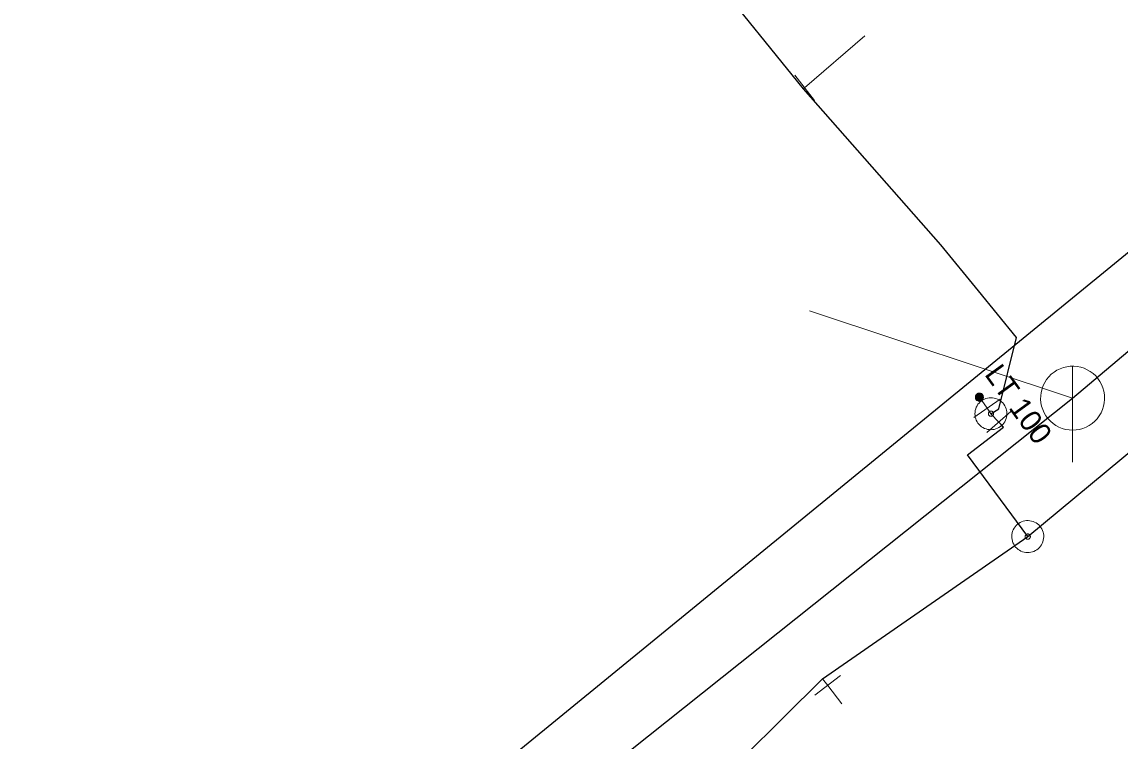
# Model space of a CAD drawing. Extents: x -688296 to -687852, y -973332 to -972816.
# Drawn here: x -688174.53 to -688140.22, y -973095.48 to -973073.01 of the extents above; entities that cross this region are included whole.
import ezdxf
from ezdxf.enums import TextEntityAlignment as Align

# ---------------------------------------------------------------- set-up
doc = ezdxf.new("R2010")
doc.units = 0
doc.header["$LTSCALE"] = 0.27
for name, color, linetype, lineweight in [('1', 7, 'Continuous', 25), ('11', 7, 'Continuous', 13), ('13', 7, 'Continuous', 13), ('14', 7, 'Continuous', 13), ('17', 7, 'Continuous', 25), ('22', 7, 'Continuous', 13), ('34', 7, 'Continuous', 13), ('47', 7, 'Continuous', 13), ('9', 7, 'Continuous', 13)]:
    doc.layers.add(name, color=color, linetype=linetype, lineweight=lineweight)

msp = doc.modelspace()

# ---------------------------------------------------------------- linework, layer by layer
at = {"layer": '11'}
msp.add_line((-688149.932, -973082.04), (-688141.706, -973084.763), dxfattribs=at)
at = {"layer": '13'}
for p, q in [((-688150.079, -973075.067), (-688148.199, -973073.44)), ((-688149.359, -973093.739), (-688148.92, -973094.32))]:
    msp.add_line(p, q, dxfattribs=at)
at = {"layer": '14', "lineweight": 25}
for p, q in [((-688141.707, -973084.764), (-688118.48, -973065.11)), ((-688173.864, -973110.353), (-688141.707, -973084.764))]:
    msp.add_line(p, q, dxfattribs=at)
at = {"layer": '14'}
for p, q in [((-688150.12, -973075.1), (-688150.079, -973075.067)), ((-688149.52, -973093.53), (-688149.359, -973093.739))]:
    msp.add_line(p, q, dxfattribs=at)
msp.add_lwpolyline([(-688144.01, -973085.51), (-688144.259, -973085.25), (-688144.379, -973085.079), (-688144.62, -973084.73)], dxfattribs=at)
at = {"layer": '17'}
for points in [[(-688123.609, -972815.609), (-688135.91, -972839.761), (-688146.524, -972867.704), (-688149.164, -972878.87), (-688150.368, -972974.473), (-688134.778, -973051.136), (-688125.903, -973068.701), (-688203.651, -973132.27), (-688148.612, -973199.748), (-688078.631, -973291.807), (-688049.631, -973331.642)], [(-688144.259, -973085.25), (-688144.01, -973085.1), (-688143.456, -973082.873), (-688144.649, -973081.41), (-688145.82, -973079.969), (-688150.12, -973075.1), (-688167.42, -973053.719)], [(-688143.109, -973089.09), (-688129.52, -973077.82), (-688116.32, -973067.34), (-688115.17, -973065.85)], [(-688143.109, -973089.09), (-688144.989, -973086.539), (-688143.87, -973085.67), (-688143.94, -973085.59), (-688144.01, -973085.51)], [(-688204.44, -973139.53), (-688204.19, -973139.309), (-688203.89, -973139.05), (-688177.64, -973116.5), (-688162.42, -973104.039), (-688153.219, -973097.199), (-688149.52, -973093.53), (-688143.109, -973089.09)]]:
    msp.add_lwpolyline(points, dxfattribs=at)
at = {"layer": '22'}
msp.add_line((-688141.707, -973086.764), (-688141.706, -973083.764), dxfattribs=at)
msp.add_lwpolyline([(-688140.707, -973084.764), (-688140.712, -973084.655), (-688140.73, -973084.547), (-688140.76, -973084.441), (-688140.8, -973084.34), (-688140.852, -973084.243), (-688140.914, -973084.153), (-688140.986, -973084.07), (-688141.066, -973083.996), (-688141.154, -973083.93), (-688141.248, -973083.875), (-688141.348, -973083.83), (-688141.453, -973083.797), (-688141.56, -973083.775), (-688141.669, -973083.765), (-688141.779, -973083.767), (-688141.887, -973083.781), (-688141.994, -973083.806), (-688142.097, -973083.843), (-688142.195, -973083.892), (-688142.287, -973083.95), (-688142.373, -973084.019), (-688142.45, -973084.096), (-688142.519, -973084.182), (-688142.578, -973084.274), (-688142.626, -973084.372), (-688142.663, -973084.475), (-688142.689, -973084.582), (-688142.703, -973084.69), (-688142.706, -973084.8), (-688142.696, -973084.909), (-688142.675, -973085.016), (-688142.641, -973085.12), (-688142.597, -973085.22), (-688142.542, -973085.315), (-688142.476, -973085.403), (-688142.402, -973085.483), (-688142.319, -973085.555), (-688142.229, -973085.617), (-688142.133, -973085.669), (-688142.031, -973085.71), (-688141.926, -973085.74), (-688141.818, -973085.758), (-688141.708, -973085.764), (-688141.599, -973085.758), (-688141.491, -973085.74), (-688141.386, -973085.711), (-688141.284, -973085.67), (-688141.187, -973085.618), (-688141.097, -973085.556), (-688141.014, -973085.485), (-688140.939, -973085.405), (-688140.874, -973085.317), (-688140.818, -973085.223), (-688140.774, -973085.123), (-688140.74, -973085.019), (-688140.718, -973084.911), (-688140.708, -973084.802)], close=True, dxfattribs=at)
at = {"layer": '34'}
for p, q in [((-688150.39, -973074.676), (-688149.767, -973075.458)), ((-688144.788, -973085.365), (-688143.968, -973084.793)), ((-688143.637, -973085.176), (-688144.383, -973085.842)), ((-688148.961, -973093.435), (-688149.757, -973094.041))]:
    msp.add_line(p, q, dxfattribs=at)
at = {"layer": '47'}
for points in [[(-688144.553, -973084.845), (-688144.593, -973084.879), (-688144.631, -973084.916), (-688144.663, -973084.956), (-688144.692, -973085), (-688144.716, -973085.047), (-688144.734, -973085.096), (-688144.747, -973085.146), (-688144.755, -973085.198), (-688144.758, -973085.25), (-688144.756, -973085.303), (-688144.747, -973085.355), (-688144.733, -973085.405), (-688144.715, -973085.454), (-688144.691, -973085.5), (-688144.663, -973085.544), (-688144.629, -973085.584), (-688144.592, -973085.622), (-688144.551, -973085.655), (-688144.508, -973085.683), (-688144.461, -973085.707), (-688144.412, -973085.725), (-688144.361, -973085.739), (-688144.309, -973085.747), (-688144.257, -973085.75), (-688144.205, -973085.747), (-688144.153, -973085.738), (-688144.103, -973085.725), (-688144.054, -973085.706), (-688144.008, -973085.682), (-688143.964, -973085.654), (-688143.924, -973085.62), (-688143.886, -973085.583), (-688143.853, -973085.543), (-688143.825, -973085.499), (-688143.801, -973085.452), (-688143.782, -973085.404), (-688143.769, -973085.353), (-688143.761, -973085.301), (-688143.758, -973085.248), (-688143.761, -973085.196), (-688143.77, -973085.144), (-688143.783, -973085.094), (-688143.802, -973085.045), (-688143.826, -973084.999), (-688143.854, -973084.955), (-688143.888, -973084.915), (-688143.925, -973084.877), (-688143.965, -973084.845), (-688144.009, -973084.816), (-688144.056, -973084.792), (-688144.104, -973084.773), (-688144.155, -973084.76), (-688144.206, -973084.752), (-688144.259, -973084.75), (-688144.312, -973084.752), (-688144.364, -973084.761), (-688144.413, -973084.774), (-688144.463, -973084.793), (-688144.509, -973084.817)], [(-688144.307, -973085.183), (-688144.314, -973085.189), (-688144.319, -973085.195), (-688144.325, -973085.201), (-688144.329, -973085.208), (-688144.333, -973085.216), (-688144.336, -973085.224), (-688144.339, -973085.233), (-688144.34, -973085.241), (-688144.34, -973085.25), (-688144.34, -973085.258), (-688144.339, -973085.267), (-688144.336, -973085.275), (-688144.333, -973085.283), (-688144.33, -973085.291), (-688144.325, -973085.298), (-688144.319, -973085.305), (-688144.313, -973085.31), (-688144.307, -973085.316), (-688144.3, -973085.32), (-688144.292, -973085.324), (-688144.284, -973085.327), (-688144.275, -973085.33), (-688144.267, -973085.331), (-688144.258, -973085.332), (-688144.25, -973085.331), (-688144.241, -973085.33), (-688144.233, -973085.327), (-688144.225, -973085.324), (-688144.217, -973085.321), (-688144.21, -973085.316), (-688144.203, -973085.31), (-688144.198, -973085.304), (-688144.192, -973085.298), (-688144.188, -973085.291), (-688144.184, -973085.283), (-688144.18, -973085.275), (-688144.178, -973085.266), (-688144.177, -973085.258), (-688144.176, -973085.249), (-688144.177, -973085.241), (-688144.178, -973085.232), (-688144.181, -973085.224), (-688144.184, -973085.216), (-688144.187, -973085.208), (-688144.192, -973085.201), (-688144.198, -973085.194), (-688144.204, -973085.189), (-688144.21, -973085.183), (-688144.217, -973085.179), (-688144.225, -973085.175), (-688144.233, -973085.171), (-688144.242, -973085.169), (-688144.25, -973085.168), (-688144.259, -973085.168), (-688144.267, -973085.168), (-688144.276, -973085.169), (-688144.284, -973085.172), (-688144.292, -973085.175), (-688144.3, -973085.178)], [(-688142.697, -973088.805), (-688142.73, -973088.764), (-688142.766, -973088.726), (-688142.806, -973088.692), (-688142.848, -973088.662), (-688142.895, -973088.637), (-688142.944, -973088.618), (-688142.994, -973088.604), (-688143.045, -973088.594), (-688143.097, -973088.59), (-688143.15, -973088.591), (-688143.202, -973088.598), (-688143.252, -973088.611), (-688143.301, -973088.628), (-688143.349, -973088.651), (-688143.393, -973088.678), (-688143.434, -973088.711), (-688143.472, -973088.747), (-688143.506, -973088.787), (-688143.536, -973088.829), (-688143.561, -973088.876), (-688143.58, -973088.925), (-688143.595, -973088.975), (-688143.604, -973089.027), (-688143.609, -973089.078), (-688143.607, -973089.131), (-688143.6, -973089.183), (-688143.587, -973089.234), (-688143.57, -973089.282), (-688143.547, -973089.33), (-688143.52, -973089.374), (-688143.487, -973089.415), (-688143.451, -973089.453), (-688143.412, -973089.488), (-688143.369, -973089.517), (-688143.322, -973089.542), (-688143.274, -973089.562), (-688143.224, -973089.577), (-688143.172, -973089.586), (-688143.12, -973089.59), (-688143.067, -973089.588), (-688143.015, -973089.581), (-688142.965, -973089.569), (-688142.916, -973089.551), (-688142.868, -973089.528), (-688142.824, -973089.501), (-688142.783, -973089.468), (-688142.745, -973089.432), (-688142.711, -973089.393), (-688142.681, -973089.35), (-688142.656, -973089.303), (-688142.636, -973089.255), (-688142.622, -973089.205), (-688142.613, -973089.154), (-688142.609, -973089.101), (-688142.61, -973089.048), (-688142.617, -973088.996), (-688142.63, -973088.946), (-688142.647, -973088.897), (-688142.67, -973088.849)], [(-688143.041, -973089.043), (-688143.046, -973089.035), (-688143.052, -973089.03), (-688143.059, -973089.025), (-688143.066, -973089.02), (-688143.073, -973089.015), (-688143.082, -973089.012), (-688143.09, -973089.01), (-688143.098, -973089.008), (-688143.107, -973089.008), (-688143.115, -973089.008), (-688143.124, -973089.009), (-688143.132, -973089.011), (-688143.14, -973089.014), (-688143.148, -973089.017), (-688143.155, -973089.022), (-688143.163, -973089.027), (-688143.168, -973089.033), (-688143.173, -973089.04), (-688143.178, -973089.047), (-688143.183, -973089.054), (-688143.186, -973089.063), (-688143.188, -973089.071), (-688143.19, -973089.079), (-688143.191, -973089.088), (-688143.19, -973089.096), (-688143.189, -973089.105), (-688143.187, -973089.113), (-688143.184, -973089.121), (-688143.181, -973089.129), (-688143.176, -973089.136), (-688143.171, -973089.144), (-688143.165, -973089.149), (-688143.158, -973089.154), (-688143.151, -973089.159), (-688143.144, -973089.164), (-688143.136, -973089.167), (-688143.127, -973089.169), (-688143.119, -973089.171), (-688143.11, -973089.172), (-688143.102, -973089.171), (-688143.093, -973089.17), (-688143.085, -973089.168), (-688143.077, -973089.165), (-688143.069, -973089.162), (-688143.062, -973089.157), (-688143.054, -973089.152), (-688143.049, -973089.146), (-688143.044, -973089.139), (-688143.039, -973089.132), (-688143.034, -973089.125), (-688143.031, -973089.117), (-688143.029, -973089.108), (-688143.027, -973089.1), (-688143.027, -973089.091), (-688143.027, -973089.083), (-688143.028, -973089.074), (-688143.03, -973089.066), (-688143.033, -973089.058), (-688143.036, -973089.05)]]:
    msp.add_lwpolyline(points, close=True, dxfattribs=at)
at = {"layer": '9'}
for points in [[(-688144.746, -973084.73), (-688144.746, -973084.743), (-688144.744, -973084.756), (-688144.741, -973084.769), (-688144.736, -973084.781), (-688144.73, -973084.793), (-688144.723, -973084.804), (-688144.715, -973084.814), (-688144.705, -973084.824), (-688144.695, -973084.832), (-688144.684, -973084.839), (-688144.672, -973084.845), (-688144.66, -973084.85), (-688144.647, -973084.853), (-688144.634, -973084.855), (-688144.621, -973084.857), (-688144.608, -973084.856), (-688144.595, -973084.854), (-688144.582, -973084.851), (-688144.57, -973084.846), (-688144.558, -973084.84), (-688144.547, -973084.833), (-688144.537, -973084.825), (-688144.527, -973084.815), (-688144.519, -973084.805), (-688144.512, -973084.794), (-688144.506, -973084.782), (-688144.501, -973084.77), (-688144.498, -973084.757), (-688144.496, -973084.744), (-688144.494, -973084.731), (-688144.495, -973084.718), (-688144.497, -973084.705), (-688144.5, -973084.692), (-688144.505, -973084.68), (-688144.511, -973084.668), (-688144.518, -973084.657), (-688144.526, -973084.647), (-688144.536, -973084.637), (-688144.546, -973084.629), (-688144.557, -973084.622), (-688144.569, -973084.616), (-688144.581, -973084.611), (-688144.594, -973084.608), (-688144.607, -973084.606), (-688144.62, -973084.605), (-688144.633, -973084.605), (-688144.646, -973084.607), (-688144.659, -973084.61), (-688144.671, -973084.615), (-688144.683, -973084.621), (-688144.694, -973084.628), (-688144.704, -973084.636), (-688144.714, -973084.646), (-688144.722, -973084.656), (-688144.729, -973084.667), (-688144.735, -973084.679), (-688144.74, -973084.691), (-688144.743, -973084.704), (-688144.745, -973084.717)], [(-688144.726, -973084.73), (-688144.727, -973084.741), (-688144.725, -973084.752), (-688144.722, -973084.763), (-688144.718, -973084.773), (-688144.713, -973084.783), (-688144.707, -973084.792), (-688144.7, -973084.801), (-688144.692, -973084.809), (-688144.683, -973084.816), (-688144.674, -973084.822), (-688144.664, -973084.827), (-688144.654, -973084.831), (-688144.643, -973084.834), (-688144.632, -973084.837), (-688144.621, -973084.837), (-688144.61, -973084.837), (-688144.599, -973084.835), (-688144.588, -973084.832), (-688144.578, -973084.828), (-688144.568, -973084.823), (-688144.559, -973084.817), (-688144.55, -973084.81), (-688144.542, -973084.802), (-688144.535, -973084.793), (-688144.529, -973084.784), (-688144.524, -973084.774), (-688144.52, -973084.764), (-688144.517, -973084.753), (-688144.515, -973084.742), (-688144.514, -973084.731), (-688144.514, -973084.72), (-688144.516, -973084.709), (-688144.519, -973084.698), (-688144.523, -973084.688), (-688144.528, -973084.678), (-688144.534, -973084.669), (-688144.541, -973084.66), (-688144.549, -973084.652), (-688144.558, -973084.645), (-688144.567, -973084.639), (-688144.577, -973084.634), (-688144.587, -973084.63), (-688144.598, -973084.627), (-688144.608, -973084.625), (-688144.62, -973084.625), (-688144.631, -973084.624), (-688144.642, -973084.626), (-688144.653, -973084.629), (-688144.663, -973084.633), (-688144.673, -973084.638), (-688144.682, -973084.644), (-688144.691, -973084.651), (-688144.699, -973084.659), (-688144.706, -973084.668), (-688144.712, -973084.677), (-688144.717, -973084.687), (-688144.721, -973084.697), (-688144.724, -973084.708), (-688144.726, -973084.719)], [(-688144.707, -973084.73), (-688144.707, -973084.739), (-688144.706, -973084.748), (-688144.703, -973084.757), (-688144.7, -973084.765), (-688144.696, -973084.773), (-688144.691, -973084.781), (-688144.684, -973084.788), (-688144.679, -973084.794), (-688144.672, -973084.8), (-688144.664, -973084.805), (-688144.656, -973084.809), (-688144.648, -973084.812), (-688144.639, -973084.815), (-688144.63, -973084.816), (-688144.621, -973084.818), (-688144.612, -973084.817), (-688144.603, -973084.816), (-688144.594, -973084.813), (-688144.586, -973084.81), (-688144.578, -973084.806), (-688144.57, -973084.801), (-688144.563, -973084.795), (-688144.557, -973084.789), (-688144.551, -973084.782), (-688144.546, -973084.774), (-688144.542, -973084.766), (-688144.539, -973084.758), (-688144.536, -973084.749), (-688144.535, -973084.74), (-688144.532, -973084.731), (-688144.534, -973084.722), (-688144.535, -973084.713), (-688144.538, -973084.704), (-688144.541, -973084.696), (-688144.545, -973084.688), (-688144.55, -973084.68), (-688144.556, -973084.673), (-688144.562, -973084.667), (-688144.569, -973084.661), (-688144.577, -973084.656), (-688144.585, -973084.652), (-688144.593, -973084.649), (-688144.602, -973084.646), (-688144.611, -973084.645), (-688144.62, -973084.644), (-688144.629, -973084.644), (-688144.638, -973084.645), (-688144.647, -973084.648), (-688144.655, -973084.651), (-688144.663, -973084.655), (-688144.671, -973084.66), (-688144.678, -973084.666), (-688144.684, -973084.672), (-688144.69, -973084.679), (-688144.695, -973084.687), (-688144.699, -973084.695), (-688144.702, -973084.703), (-688144.705, -973084.712), (-688144.706, -973084.721)], [(-688144.687, -973084.73), (-688144.687, -973084.737), (-688144.686, -973084.744), (-688144.684, -973084.751), (-688144.682, -973084.757), (-688144.679, -973084.763), (-688144.675, -973084.769), (-688144.671, -973084.775), (-688144.666, -973084.78), (-688144.66, -973084.784), (-688144.654, -973084.788), (-688144.648, -973084.791), (-688144.642, -973084.794), (-688144.635, -973084.795), (-688144.628, -973084.798), (-688144.621, -973084.798), (-688144.614, -973084.798), (-688144.607, -973084.796), (-688144.6, -973084.795), (-688144.594, -973084.792), (-688144.587, -973084.789), (-688144.582, -973084.785), (-688144.576, -973084.781), (-688144.571, -973084.776), (-688144.567, -973084.77), (-688144.563, -973084.764), (-688144.559, -973084.758), (-688144.557, -973084.752), (-688144.555, -973084.745), (-688144.554, -973084.738), (-688144.553, -973084.731), (-688144.553, -973084.724), (-688144.554, -973084.717), (-688144.556, -973084.71), (-688144.559, -973084.704), (-688144.562, -973084.697), (-688144.566, -973084.692), (-688144.57, -973084.686), (-688144.575, -973084.681), (-688144.581, -973084.677), (-688144.586, -973084.673), (-688144.593, -973084.67), (-688144.599, -973084.667), (-688144.606, -973084.665), (-688144.613, -973084.664), (-688144.62, -973084.664), (-688144.627, -973084.664), (-688144.634, -973084.664), (-688144.641, -973084.666), (-688144.647, -973084.669), (-688144.653, -973084.672), (-688144.659, -973084.676), (-688144.665, -973084.68), (-688144.67, -973084.685), (-688144.674, -973084.691), (-688144.678, -973084.696), (-688144.681, -973084.703), (-688144.684, -973084.709), (-688144.684, -973084.716), (-688144.687, -973084.723)], [(-688144.667, -973084.73), (-688144.667, -973084.735), (-688144.667, -973084.74), (-688144.666, -973084.745), (-688144.664, -973084.749), (-688144.662, -973084.754), (-688144.659, -973084.758), (-688144.656, -973084.761), (-688144.652, -973084.765), (-688144.649, -973084.768), (-688144.645, -973084.771), (-688144.64, -973084.773), (-688144.636, -973084.775), (-688144.631, -973084.776), (-688144.626, -973084.778), (-688144.621, -973084.778), (-688144.616, -973084.778), (-688144.611, -973084.777), (-688144.606, -973084.776), (-688144.602, -973084.774), (-688144.597, -973084.772), (-688144.593, -973084.769), (-688144.589, -973084.766), (-688144.586, -973084.762), (-688144.583, -973084.759), (-688144.58, -973084.755), (-688144.578, -973084.75), (-688144.576, -973084.746), (-688144.575, -973084.741), (-688144.574, -973084.736), (-688144.573, -973084.731), (-688144.573, -973084.726), (-688144.574, -973084.721), (-688144.575, -973084.716), (-688144.577, -973084.712), (-688144.579, -973084.707), (-688144.582, -973084.703), (-688144.585, -973084.699), (-688144.588, -973084.696), (-688144.592, -973084.693), (-688144.596, -973084.69), (-688144.601, -973084.688), (-688144.605, -973084.686), (-688144.61, -973084.685), (-688144.615, -973084.684), (-688144.62, -973084.684), (-688144.625, -973084.684), (-688144.63, -973084.685), (-688144.635, -973084.685), (-688144.639, -973084.687), (-688144.644, -973084.689), (-688144.648, -973084.692), (-688144.651, -973084.695), (-688144.655, -973084.698), (-688144.657, -973084.702), (-688144.661, -973084.706), (-688144.663, -973084.711), (-688144.665, -973084.715), (-688144.666, -973084.72), (-688144.667, -973084.725)], [(-688144.647, -973084.73), (-688144.647, -973084.733), (-688144.648, -973084.736), (-688144.647, -973084.738), (-688144.646, -973084.741), (-688144.645, -973084.744), (-688144.643, -973084.746), (-688144.641, -973084.748), (-688144.639, -973084.75), (-688144.637, -973084.752), (-688144.635, -973084.754), (-688144.632, -973084.756), (-688144.629, -973084.757), (-688144.627, -973084.757), (-688144.624, -973084.758), (-688144.621, -973084.758), (-688144.618, -973084.758), (-688144.615, -973084.758), (-688144.612, -973084.757), (-688144.61, -973084.756), (-688144.607, -973084.755), (-688144.605, -973084.753), (-688144.602, -973084.751), (-688144.6, -973084.749), (-688144.599, -973084.747), (-688144.597, -973084.745), (-688144.596, -973084.742), (-688144.594, -973084.739), (-688144.594, -973084.737), (-688144.593, -973084.734), (-688144.592, -973084.731), (-688144.593, -973084.728), (-688144.593, -973084.725), (-688144.594, -973084.722), (-688144.595, -973084.72), (-688144.596, -973084.717), (-688144.598, -973084.715), (-688144.599, -973084.712), (-688144.601, -973084.71), (-688144.604, -973084.709), (-688144.606, -973084.707), (-688144.608, -973084.706), (-688144.611, -973084.705), (-688144.614, -973084.704), (-688144.617, -973084.704), (-688144.62, -973084.703), (-688144.623, -973084.704), (-688144.626, -973084.703), (-688144.628, -973084.705), (-688144.631, -973084.705), (-688144.634, -973084.706), (-688144.636, -973084.708), (-688144.638, -973084.709), (-688144.64, -973084.711), (-688144.642, -973084.714), (-688144.644, -973084.716), (-688144.645, -973084.719), (-688144.646, -973084.721), (-688144.647, -973084.724), (-688144.647, -973084.727)], [(-688144.628, -973084.73), (-688144.628, -973084.732), (-688144.628, -973084.732), (-688144.627, -973084.732), (-688144.627, -973084.734), (-688144.628, -973084.735), (-688144.626, -973084.735), (-688144.626, -973084.735), (-688144.626, -973084.737), (-688144.626, -973084.737), (-688144.625, -973084.738), (-688144.623, -973084.738), (-688144.623, -973084.738), (-688144.623, -973084.739), (-688144.621, -973084.739), (-688144.621, -973084.739), (-688144.62, -973084.739), (-688144.619, -973084.739), (-688144.619, -973084.738), (-688144.618, -973084.738), (-688144.616, -973084.738), (-688144.616, -973084.737), (-688144.616, -973084.737), (-688144.615, -973084.736), (-688144.615, -973084.736), (-688144.613, -973084.735), (-688144.613, -973084.734), (-688144.612, -973084.733), (-688144.612, -973084.733), (-688144.612, -973084.732), (-688144.612, -973084.731), (-688144.612, -973084.73), (-688144.612, -973084.729), (-688144.612, -973084.729), (-688144.613, -973084.728), (-688144.613, -973084.727), (-688144.614, -973084.726), (-688144.614, -973084.726), (-688144.615, -973084.725), (-688144.615, -973084.725), (-688144.616, -973084.724), (-688144.617, -973084.724), (-688144.618, -973084.723), (-688144.618, -973084.723), (-688144.619, -973084.723), (-688144.62, -973084.723), (-688144.621, -973084.723), (-688144.622, -973084.723), (-688144.622, -973084.723), (-688144.623, -973084.724), (-688144.624, -973084.723), (-688144.625, -973084.725), (-688144.625, -973084.725), (-688144.626, -973084.725), (-688144.626, -973084.725), (-688144.627, -973084.727), (-688144.627, -973084.728), (-688144.627, -973084.729), (-688144.628, -973084.729), (-688144.628, -973084.73)]]:
    msp.add_lwpolyline(points, close=True, dxfattribs=at)

# ---------------------------------------------------------------- texts
at = {"layer": '1'}
msp.add_text('LT 100', height=0.6667, rotation=306, dxfattribs=at).set_placement((-688143.6632, -973085.1446), align=Align.CENTER)
msp.add_text('LT 100', height=0.6667, rotation=306, dxfattribs=at).set_placement((-688143.6632, -973085.1446), align=Align.CENTER)
msp.add_text('LT 100', height=0.6667, rotation=306, dxfattribs=at).set_placement((-688143.6632, -973085.1446), align=Align.CENTER)
msp.add_text('LT 100', height=0.6667, rotation=306, dxfattribs=at).set_placement((-688143.6632, -973085.1446), align=Align.CENTER)
msp.add_text('LT 100', height=0.6667, rotation=306, dxfattribs=at).set_placement((-688143.6632, -973085.1446), align=Align.CENTER)

doc.saveas('drawing.dxf')
